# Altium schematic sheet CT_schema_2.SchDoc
size 271 x 273 mm
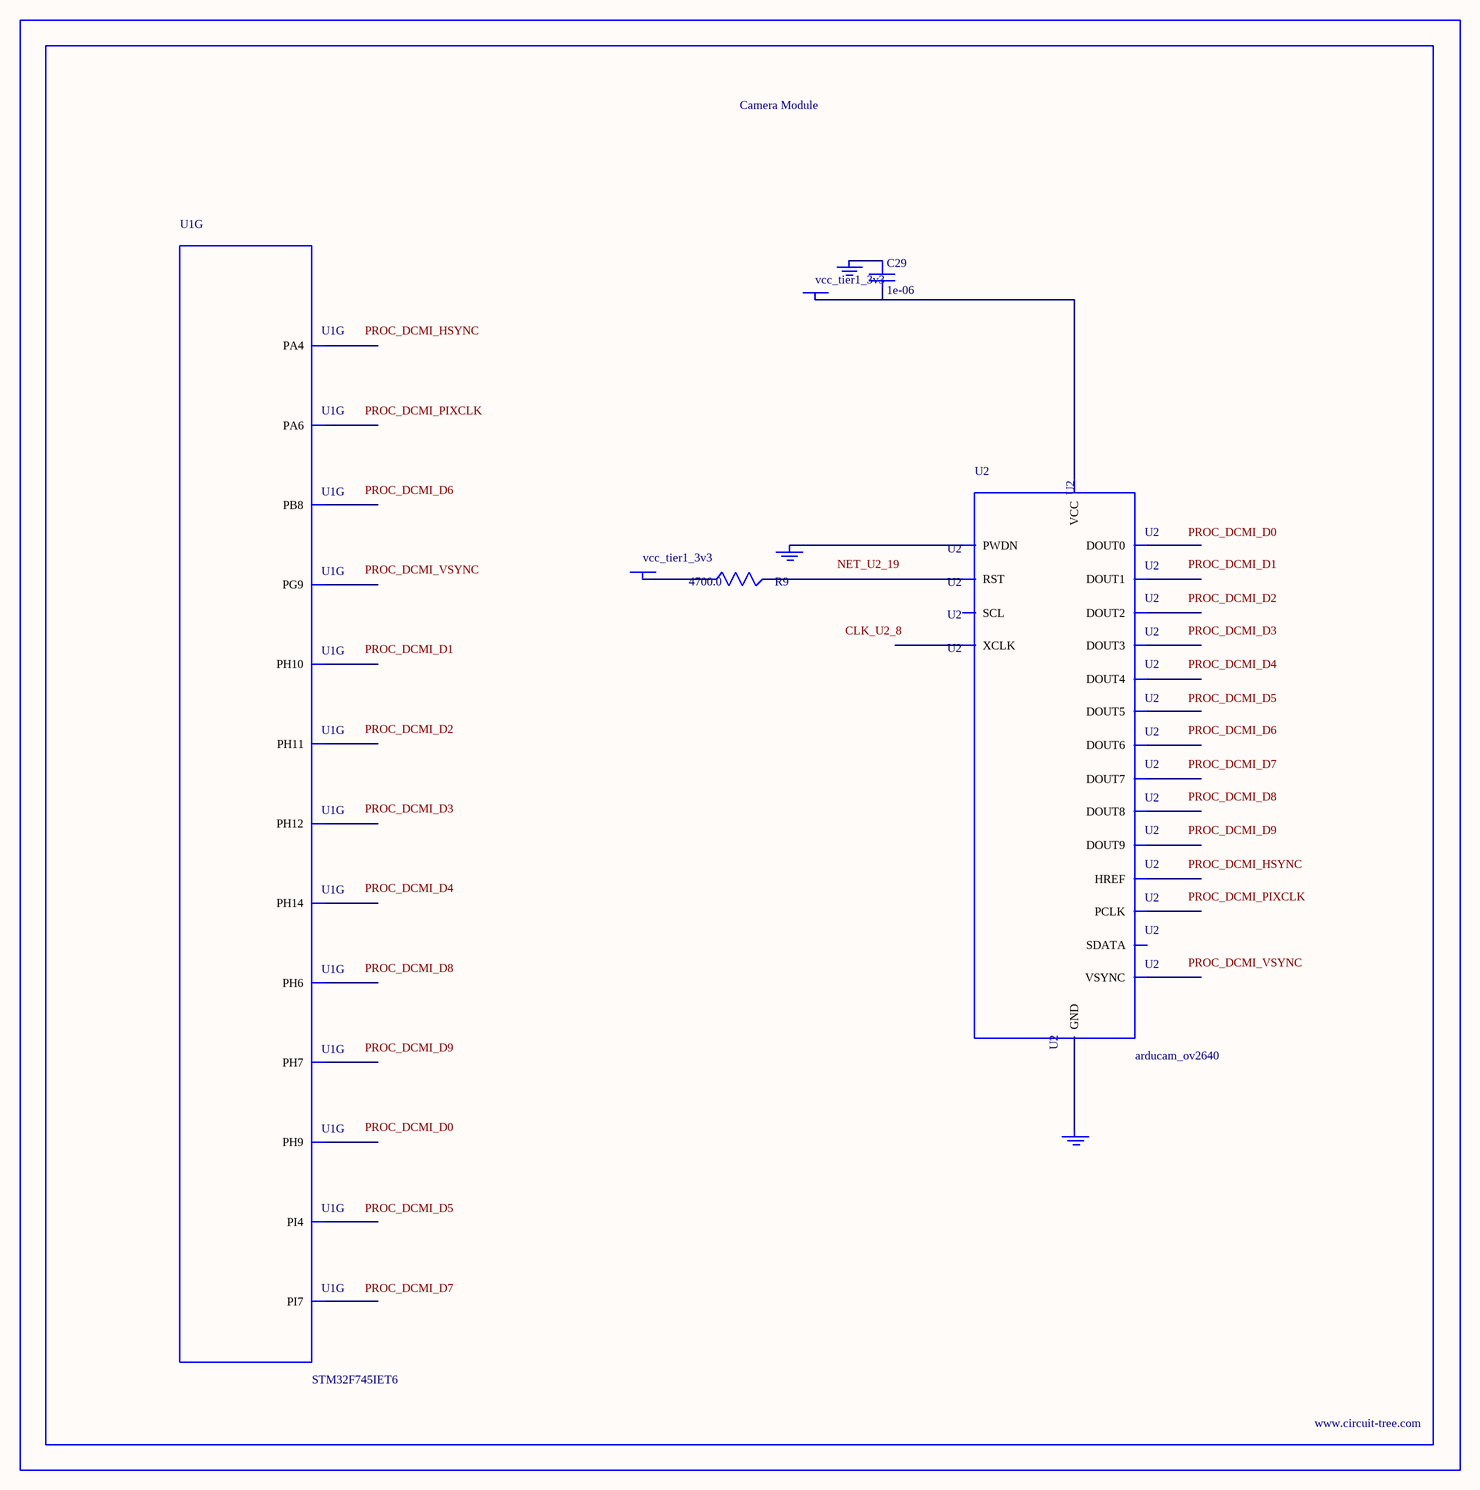
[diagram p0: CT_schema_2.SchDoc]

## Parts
BORDER1  (no value)
C29  1e-06  [C0603]
GND_INSTANCE_1_0  (no value)
GND_INSTANCE_1_1  (no value)
GND_INSTANCE_1_2  (no value)
POWER_INSTANCE_1_0  vcc_tier1_3v3
POWER_INSTANCE_1_1  vcc_tier1_3v3
R9  4700.0  [R0603]
U1  STM32F745IET6  [LQFP176]  (part G of 14)
U2  arducam_ov2640  [ARDUCAM]

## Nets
NetC29_1: C29.1 GND_INSTANCE_1_0.0(GND)
NetC29_2: C29.2 POWER_INSTANCE_1_0.0(PWR) U2.1(VCC)
NetGND_INSTANCE_1_1_0: GND_INSTANCE_1_1.0(GND) U2.20(PWDN)
NetGND_INSTANCE_1_2_0: GND_INSTANCE_1_2.0(GND) U2.2(GND)
NetPOWER_INSTANCE_1_1_0: POWER_INSTANCE_1_1.0(PWR) R9.1
NetR9_2: R9.2 U2.19(RST)

Not connected (* = marked no-connect by the designer): U1 50(PA4) 52(PA6) 83(PH6) 84(PH7) 86(PH9) 87(PH10) 88(PH11) 89(PH12) 129(PH14) 152(PG9) 167(PB8) 173(PI4) 176(PI7); U2 3(SCL) 4(SDATA) 5(VSYNC) 6(HREF) 7(PCLK) 8(XCLK) 9(DOUT9) 10(DOUT8) 11(DOUT7) 12(DOUT6) 13(DOUT5) 14(DOUT4) 15(DOUT3) 16(DOUT2) 17(DOUT1) 18(DOUT0)

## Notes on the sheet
- Labels drawn without touching a wire or pin: CLK_U2_8, NET_U2_19, PROC_DCMI_D0, PROC_DCMI_D1, PROC_DCMI_D2, PROC_DCMI_D3, PROC_DCMI_D4, PROC_DCMI_D5, PROC_DCMI_D6, PROC_DCMI_D7, PROC_DCMI_D8, PROC_DCMI_D9, PROC_DCMI_HSYNC, PROC_DCMI_PIXCLK, PROC_DCMI_VSYNC

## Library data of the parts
BORDER1 = BORDER_PAGE1
C29 = C0603C105K3RACTU
GND_INSTANCE_1_0-GND_INSTANCE_1_2 = GND
POWER_INSTANCE_1_0 POWER_INSTANCE_1_1 = PWR
R9 = RC0603JR-074K7L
